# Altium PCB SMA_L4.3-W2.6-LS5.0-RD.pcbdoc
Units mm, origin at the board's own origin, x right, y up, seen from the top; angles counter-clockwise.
Board outline 19.55 x 15.58 mm, 2 copper layers (Top Layer, Bottom Layer), stack 0 mm thick; 1 components, 0 nets, 2 pads, 0 vias.
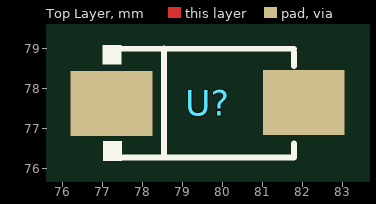
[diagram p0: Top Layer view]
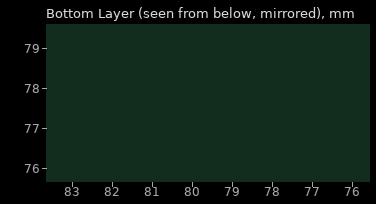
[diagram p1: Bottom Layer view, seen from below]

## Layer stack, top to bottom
Top Layer: signal copper (thickness not stored)
Bottom Layer: signal copper (thickness not stored)

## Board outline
89.404,69.85 69.85,69.85 69.85,85.43 89.404,85.43

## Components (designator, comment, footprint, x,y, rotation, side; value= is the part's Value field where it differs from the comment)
U? "" SMA_L4.3-W2.6-LS5.0-RD 79.627,77.64 r0 top

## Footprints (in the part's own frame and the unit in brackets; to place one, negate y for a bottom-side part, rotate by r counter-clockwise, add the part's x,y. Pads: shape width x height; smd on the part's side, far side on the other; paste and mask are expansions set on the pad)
SMA_L4.3-W2.6-LS5.0-RD [mm]
  rect 2.046x1.62 smd: 1(-2.404,-0.009) 2(2.404,0.009)
  silkscreen extent -2.61,-1.44 2.16,1.44

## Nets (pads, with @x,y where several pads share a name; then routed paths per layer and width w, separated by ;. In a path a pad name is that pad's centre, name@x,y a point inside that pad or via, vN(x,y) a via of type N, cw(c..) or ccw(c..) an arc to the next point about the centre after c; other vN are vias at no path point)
pads on no net: U?.1 U?.2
